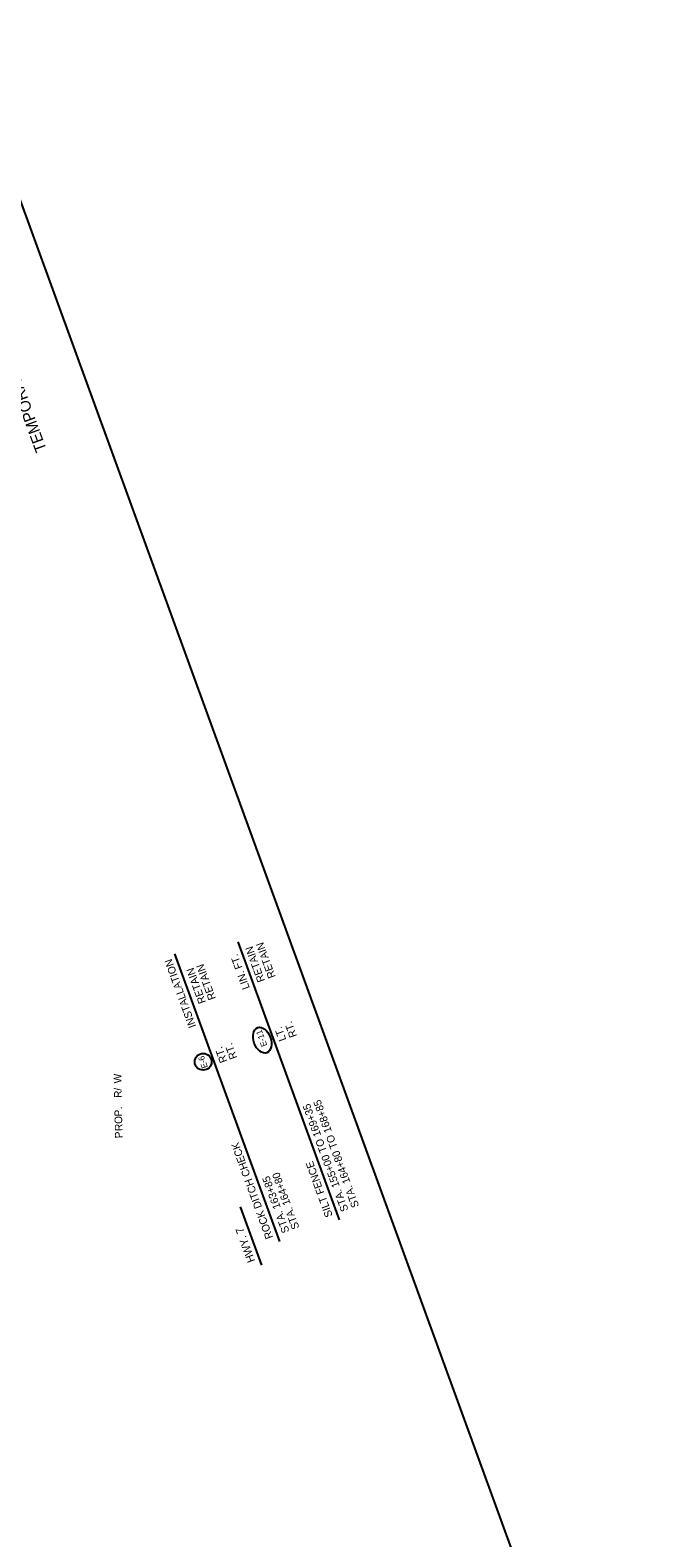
# Model space of a CAD drawing. Extents: x 986289 to 987754, y 1871116 to 1872971.
# Drawn here: x 987265 to 987754, y 1871784 to 1872971 of the extents above; entities that cross this region are included whole.
import ezdxf

# ---------------------------------------------------------------- set-up
doc = ezdxf.new("R2010")
doc.units = 0
for name, color, linetype in [('1', 7, 'Continuous'), ('44', 7, 'Continuous'), ('60', 7, 'Continuous'), ('NO PLOT', 7, 'Continuous'), ('R_Draft', 7, 'Continuous')]:
    doc.layers.add(name, color=color, linetype=linetype)

msp = doc.modelspace()

# ---------------------------------------------------------------- linework, layer by layer
at = {"layer": '1'}
msp.add_circle((987400.7, 1872158.9), 6.61, dxfattribs=at)
msp.add_ellipse((987447.2, 1872175.9), major_axis=(-3.6, 9.89), ratio=0.638788, dxfattribs=at)
at = {"layer": '44'}
for p, q in [((987507.9, 1872034.5), (987428.3, 1872253.3)), ((987461, 1872017.4), (987378.5, 1872243.9)), ((987446.9, 1871998.8), (987430.2, 1872044.7))]:
    msp.add_line(p, q, dxfattribs=at)
at = {"layer": 'NO PLOT'}
msp.add_lwpolyline([(987753.7, 1871472.1), (987208, 1872971.2), (986718.3, 1872793), (986821.2, 1872510.2), (986884.7, 1872533.2), (987030, 1872133.9), (986966.6, 1872110.8), (987064.5, 1871841.9), (987122.5, 1871863), (987239.7, 1871541), (987181.7, 1871519.9), (987263.9, 1871293.8)], close=True, dxfattribs=at)
msp.add_lwpolyline([(987753.7, 1871472.1), (987208, 1872971.2), (986718.3, 1872793), (986821.2, 1872510.2), (986884.7, 1872533.2), (987030, 1872133.9), (986966.6, 1872110.8), (987064.5, 1871841.9), (987122.5, 1871863), (987239.7, 1871541), (987181.7, 1871519.9), (987263.9, 1871293.8)], close=True, dxfattribs=at)
msp.add_lwpolyline([(987753.7, 1871472.1), (987208, 1872971.2), (986718.3, 1872793), (986821.2, 1872510.2), (986884.7, 1872533.2), (987030, 1872133.9), (986966.6, 1872110.8), (987064.5, 1871841.9), (987122.5, 1871863), (987239.7, 1871541), (987181.7, 1871519.9), (987263.9, 1871293.8)], close=True, dxfattribs=at)
msp.add_lwpolyline([(987753.7, 1871472.1), (987208, 1872971.2), (986718.3, 1872793), (986821.2, 1872510.2), (986884.7, 1872533.2), (987030, 1872133.9), (986966.6, 1872110.8), (987064.5, 1871841.9), (987122.5, 1871863), (987239.7, 1871541), (987181.7, 1871519.9), (987263.9, 1871293.8)], close=True, dxfattribs=at)
msp.add_lwpolyline([(987753.7, 1871472.1), (987208, 1872971.2), (986718.3, 1872793), (986821.2, 1872510.2), (986884.7, 1872533.2), (987030, 1872133.9), (986966.6, 1872110.8), (987064.5, 1871841.9), (987122.5, 1871863), (987239.7, 1871541), (987181.7, 1871519.9), (987263.9, 1871293.8)], close=True, dxfattribs=at)
msp.add_lwpolyline([(987753.7, 1871472.1), (987208, 1872971.2), (986718.3, 1872793), (986821.2, 1872510.2), (986884.7, 1872533.2), (987030, 1872133.9), (986966.6, 1872110.8), (987064.5, 1871841.9), (987122.5, 1871863), (987239.7, 1871541), (987181.7, 1871519.9), (987263.9, 1871293.8)], close=True, dxfattribs=at)
msp.add_lwpolyline([(987753.7, 1871472.1), (987208, 1872971.2), (986718.3, 1872793), (986821.2, 1872510.2), (986884.7, 1872533.2), (987030, 1872133.9), (986966.6, 1872110.8), (987064.5, 1871841.9), (987122.5, 1871863), (987239.7, 1871541), (987181.7, 1871519.9), (987263.9, 1871293.8)], close=True, dxfattribs=at)

# ---------------------------------------------------------------- texts
at = {"layer": '1'}
for s, p in [('E-11', (987451.2, 1872171.8)), ('E-6 ', (987404.5, 1872154.7))]:
    msp.add_text(s, height=4.8, rotation=110, dxfattribs=at).set_placement(p)
at = {"layer": '44'}
for s, height, p in [('RETAIN', 6, (987449.4, 1872222.8)), ('RETAIN', 6, (987457.8, 1872225.9)), ('INSTALLATION', 6, (987395.3, 1872186.8)), ('LIN. FT.', 6, (987437.5, 1872217.1)), ('RETAIN', 6, (987403, 1872205.9)), ('RETAIN', 6, (987410.8, 1872208.8)), ('RT.', 6, (987474.6, 1872179.2)), ('LT.', 6, (987466.2, 1872176.3)), ('RT.', 6, (987419.8, 1872159.3)), ('RT.', 6, (987427.6, 1872162.1)), ('STA. 155+00 TO 169+35', 6, (987515.1, 1872042.2)), ('STA. 164+80 TO 168+85', 6, (987523.5, 1872045.3)), ('ROCK DITCH CHECK', 6, (987455.8, 1872020.6)), ('STA. 164+80', 6, (987476.5, 1872028.2)), ('SILT FENCE      ', 6, (987502.7, 1872037.7)), ('STA. 163+85', 6, (987468.7, 1872025.3)), ('HWY. 7', 6.25, (987441.7, 1872002.1))]:
    msp.add_text(s, height=height, rotation=110, dxfattribs=at).set_placement(p)
at = {"layer": '60'}
msp.add_text('TEMPORARY EROSION CONTROL DETAILS', height=9, rotation=110, dxfattribs=at).set_placement((987277.8, 1872640.8))
at = {"layer": 'R_Draft'}
for s, p in [('W', (987336.5, 1872142)), ('/', (987336.6, 1872136.2)), ('R', (987336.7, 1872130.5)), ('P', (987337, 1872115.9)), ('.', (987336.9, 1872121.6)), ('O', (987337.1, 1872110)), ('R', (987337.3, 1872104.4)), ('P', (987337.4, 1872098.7))]:
    msp.add_text(s, height=6, rotation=91.2073, dxfattribs=at).set_placement(p)

doc.saveas('drawing.dxf')
